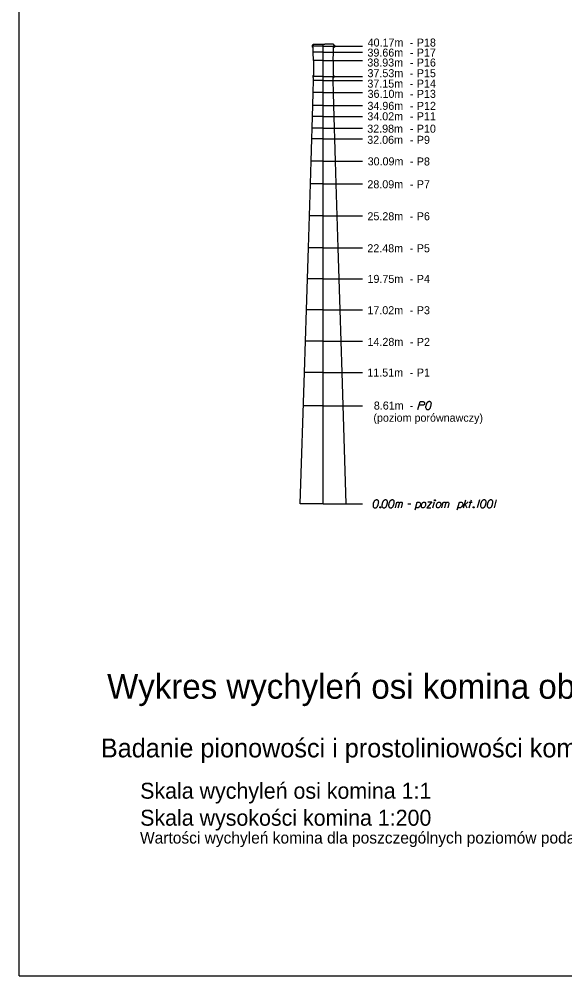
# Model space of a CAD drawing. Extents: x 138 to 264, y -75 to 121.
# Drawn here: x 196.41 to 206.91, y 2.29 to 20.71 of the extents above; entities that cross this region are included whole.
import ezdxf

# ---------------------------------------------------------------- set-up
doc = ezdxf.new("R2010")
doc.units = 0
doc.layers.add('Opisy', color=7, linetype='Continuous')
doc.layers.add('Ramka do drukowania', color=7, linetype='Continuous')

msp = doc.modelspace()

# ---------------------------------------------------------------- linework, layer by layer
at = {"layer": 'Opisy'}
for p, q in [((202.049, 20.204), (202.049, 20.185)), ((202.066, 20.204), (202.049, 20.204)), ((202.262, 20.185), (202.049, 20.185)), ((202.049, 20.185), (202.049, 20.166)), ((202.066, 20.166), (202.049, 20.166)), ((202.066, 20.222), (202.066, 20.204)), ((202.066, 20.222), (202.293, 20.222)), ((202.066, 20.072), (202.066, 20.166)), ((202.262, 11.376), (202.262, 20.222)), ((202.262, 20.185), (203.015, 20.185)), ((202.458, 20.222), (202.293, 20.222)), ((202.458, 20.222), (202.458, 20.204)), ((202.458, 20.204), (202.475, 20.204)), ((202.458, 20.166), (202.475, 20.166)), ((202.458, 20.072), (202.458, 20.166)), ((202.475, 20.204), (202.475, 20.185)), ((202.475, 20.185), (202.475, 20.166)), ((202.262, 20.072), (202.066, 20.072)), ((202.072, 19.912), (202.066, 20.072)), ((202.262, 19.912), (202.072, 19.912)), ((202.072, 19.912), (202.072, 19.624)), ((202.262, 20.072), (203.015, 20.072)), ((202.262, 19.912), (203.015, 19.912)), ((202.452, 19.912), (202.458, 20.072)), ((202.452, 19.912), (202.452, 19.624)), ((202.059, 19.624), (202.059, 19.605)), ((202.059, 19.624), (202.072, 19.624)), ((202.262, 19.605), (202.059, 19.605)), ((202.059, 19.605), (202.059, 19.586)), ((202.074, 19.586), (202.059, 19.586)), ((202.072, 19.522), (202.074, 19.586)), ((202.262, 19.605), (203.015, 19.605)), ((202.452, 19.522), (202.45, 19.586)), ((202.45, 19.586), (202.465, 19.586)), ((202.465, 19.624), (202.452, 19.624)), ((202.465, 19.624), (202.465, 19.605)), ((202.465, 19.605), (202.465, 19.586)), ((202.066, 19.291), (202.072, 19.522)), ((202.262, 19.522), (202.072, 19.522)), ((202.262, 19.522), (203.015, 19.522)), ((202.458, 19.291), (202.452, 19.522)), ((202.059, 19.041), (202.066, 19.291)), ((202.262, 19.291), (202.066, 19.291)), ((202.262, 19.291), (203.015, 19.291)), ((202.465, 19.041), (202.458, 19.291)), ((202.053, 18.835), (202.059, 19.041)), ((202.262, 19.041), (202.059, 19.041)), ((202.262, 19.041), (203.015, 19.041)), ((202.472, 18.835), (202.465, 19.041)), ((202.047, 18.607), (202.053, 18.835)), ((202.262, 18.835), (202.053, 18.835)), ((202.262, 18.835), (203.015, 18.835)), ((202.477, 18.607), (202.472, 18.835)), ((202.04, 18.405), (202.047, 18.607)), ((202.262, 18.607), (202.047, 18.607)), ((202.262, 18.607), (203.015, 18.607)), ((202.485, 18.405), (202.477, 18.607)), ((202.028, 17.973), (202.04, 18.405)), ((202.262, 18.405), (202.04, 18.405)), ((202.262, 18.405), (203.015, 18.405)), ((202.497, 17.973), (202.485, 18.405)), ((202.014, 17.535), (202.028, 17.973)), ((202.262, 17.973), (202.028, 17.973)), ((202.262, 17.973), (203.015, 17.973)), ((202.51, 17.535), (202.497, 17.973)), ((201.997, 16.918), (202.014, 17.535)), ((202.262, 17.535), (202.014, 17.535)), ((202.262, 17.535), (203.015, 17.535)), ((202.527, 16.918), (202.51, 17.535)), ((201.977, 16.305), (201.997, 16.918)), ((202.262, 16.918), (201.997, 16.918)), ((202.262, 16.918), (203.015, 16.918)), ((202.547, 16.305), (202.527, 16.918)), ((201.958, 15.706), (201.977, 16.305)), ((202.262, 16.305), (201.977, 16.305)), ((202.262, 16.305), (203.015, 16.305)), ((202.566, 15.706), (202.547, 16.305)), ((201.94, 15.108), (201.958, 15.706)), ((202.262, 15.706), (201.958, 15.706)), ((202.262, 15.706), (203.015, 15.706)), ((202.584, 15.108), (202.566, 15.706)), ((201.921, 14.506), (201.94, 15.108)), ((202.262, 15.108), (201.94, 15.108)), ((202.262, 15.108), (203.015, 15.108)), ((202.603, 14.506), (202.584, 15.108)), ((201.901, 13.9), (201.921, 14.506)), ((202.262, 14.506), (201.921, 14.506)), ((202.262, 14.506), (203.015, 14.506)), ((202.623, 13.9), (202.603, 14.506)), ((201.819, 11.376), (201.901, 13.9)), ((202.262, 13.9), (201.901, 13.9)), ((202.262, 13.9), (203.015, 13.9)), ((202.705, 11.376), (202.623, 13.9)), ((202.262, 13.263), (201.881, 13.263)), ((202.262, 13.263), (203.015, 13.263)), ((202.262, 11.376), (201.819, 11.376)), ((202.262, 11.376), (203.015, 11.376))]:
    msp.add_line(p, q, dxfattribs=at)
for points in [[(204.084, 13.189), (204.126, 13.343), (204.178, 13.343), (204.185, 13.342), (204.189, 13.34), (204.196, 13.337), (204.201, 13.333), (204.205, 13.328), (204.208, 13.322), (204.211, 13.314), (204.212, 13.306), (204.211, 13.3), (204.209, 13.295), (204.207, 13.291), (204.205, 13.287), (204.201, 13.282), (204.196, 13.278), (204.192, 13.276), (204.186, 13.274), (204.18, 13.272), (204.107, 13.272)], [(204.305, 13.343), (204.303, 13.343), (204.296, 13.342), (204.291, 13.34), (204.287, 13.339), (204.281, 13.337), (204.274, 13.333), (204.268, 13.329), (204.262, 13.325), (204.258, 13.32), (204.254, 13.314), (204.251, 13.308), (204.247, 13.3), (204.245, 13.295), (204.242, 13.288), (204.239, 13.276), (204.235, 13.258), (204.232, 13.243), (204.232, 13.23), (204.234, 13.22), (204.239, 13.209), (204.242, 13.203), (204.248, 13.196), (204.256, 13.191), (204.259, 13.19), (204.266, 13.189), (204.273, 13.189), (204.282, 13.19), (204.291, 13.192), (204.297, 13.196), (204.305, 13.202), (204.309, 13.206), (204.314, 13.21), (204.317, 13.215), (204.32, 13.219), (204.322, 13.225), (204.324, 13.227), (204.326, 13.234), (204.328, 13.241), (204.331, 13.248), (204.332, 13.253), (204.333, 13.257), (204.334, 13.261), (204.337, 13.272), (204.338, 13.278), (204.339, 13.285), (204.341, 13.293), (204.342, 13.304), (204.342, 13.308), (204.341, 13.312), (204.339, 13.317), (204.336, 13.325), (204.332, 13.329), (204.328, 13.333), (204.324, 13.337), (204.319, 13.339), (204.315, 13.34), (204.311, 13.342), (204.305, 13.343)], [(203.291, 11.45), (203.289, 11.45), (203.282, 11.449), (203.277, 11.448), (203.273, 11.447), (203.267, 11.444), (203.26, 11.441), (203.254, 11.437), (203.248, 11.432), (203.244, 11.427), (203.24, 11.421), (203.237, 11.415), (203.233, 11.408), (203.231, 11.403), (203.228, 11.396), (203.225, 11.384), (203.221, 11.365), (203.219, 11.351), (203.219, 11.337), (203.22, 11.328), (203.225, 11.317), (203.228, 11.311), (203.234, 11.303), (203.242, 11.299), (203.245, 11.297), (203.253, 11.296), (203.259, 11.296), (203.268, 11.297), (203.277, 11.3), (203.283, 11.303), (203.291, 11.31), (203.295, 11.313), (203.3, 11.318), (203.304, 11.323), (203.306, 11.327), (203.308, 11.333), (203.31, 11.335), (203.312, 11.341), (203.315, 11.348), (203.317, 11.356), (203.318, 11.361), (203.319, 11.364), (203.321, 11.369), (203.323, 11.38), (203.324, 11.386), (203.325, 11.392), (203.327, 11.401), (203.328, 11.412), (203.328, 11.415), (203.327, 11.42), (203.325, 11.425), (203.322, 11.432), (203.318, 11.437), (203.315, 11.441), (203.31, 11.444), (203.305, 11.447), (203.301, 11.448), (203.298, 11.449), (203.291, 11.45)], [(203.463, 11.45), (203.46, 11.45), (203.453, 11.449), (203.448, 11.448), (203.444, 11.447), (203.438, 11.444), (203.431, 11.441), (203.425, 11.437), (203.419, 11.432), (203.415, 11.427), (203.412, 11.421), (203.408, 11.415), (203.404, 11.408), (203.402, 11.403), (203.399, 11.396), (203.396, 11.384), (203.392, 11.365), (203.39, 11.351), (203.39, 11.337), (203.391, 11.328), (203.396, 11.317), (203.399, 11.311), (203.406, 11.303), (203.413, 11.299), (203.416, 11.297), (203.424, 11.296), (203.43, 11.296), (203.44, 11.297), (203.448, 11.3), (203.454, 11.303), (203.463, 11.31), (203.466, 11.313), (203.471, 11.318), (203.475, 11.323), (203.477, 11.327), (203.48, 11.333), (203.481, 11.335), (203.483, 11.341), (203.486, 11.348), (203.488, 11.356), (203.489, 11.361), (203.491, 11.364), (203.492, 11.369), (203.494, 11.38), (203.495, 11.386), (203.497, 11.392), (203.498, 11.401), (203.499, 11.412), (203.499, 11.415), (203.498, 11.42), (203.497, 11.425), (203.493, 11.432), (203.489, 11.437), (203.486, 11.441), (203.481, 11.444), (203.476, 11.447), (203.472, 11.448), (203.469, 11.449), (203.463, 11.45)], [(203.592, 11.45), (203.59, 11.45), (203.583, 11.449), (203.578, 11.448), (203.574, 11.447), (203.568, 11.444), (203.561, 11.441), (203.555, 11.437), (203.549, 11.432), (203.545, 11.427), (203.541, 11.421), (203.538, 11.415), (203.534, 11.408), (203.532, 11.403), (203.529, 11.396), (203.526, 11.384), (203.522, 11.365), (203.52, 11.351), (203.52, 11.337), (203.521, 11.328), (203.526, 11.317), (203.529, 11.311), (203.535, 11.303), (203.543, 11.299), (203.546, 11.297), (203.554, 11.296), (203.56, 11.296), (203.569, 11.297), (203.578, 11.3), (203.584, 11.303), (203.592, 11.31), (203.596, 11.313), (203.601, 11.318), (203.605, 11.323), (203.607, 11.327), (203.609, 11.333), (203.611, 11.335), (203.613, 11.341), (203.616, 11.348), (203.618, 11.356), (203.619, 11.361), (203.62, 11.364), (203.622, 11.369), (203.624, 11.38), (203.625, 11.386), (203.626, 11.392), (203.628, 11.401), (203.629, 11.412), (203.629, 11.415), (203.628, 11.42), (203.626, 11.425), (203.623, 11.432), (203.619, 11.437), (203.616, 11.441), (203.611, 11.444), (203.606, 11.447), (203.602, 11.448), (203.599, 11.449), (203.592, 11.45)], [(204.407, 11.45), (204.413, 11.45), (204.417, 11.448), (204.42, 11.443), (204.42, 11.437), (204.417, 11.432), (204.413, 11.43), (204.407, 11.43), (204.403, 11.432), (204.4, 11.437), (204.4, 11.443), (204.403, 11.448), (204.407, 11.45)], [(204.963, 11.296), (205.004, 11.45)], [(205.071, 11.296), (205.111, 11.45)], [(205.266, 11.45), (205.225, 11.296)], [(205.36, 11.45), (205.357, 11.45), (205.35, 11.449), (205.345, 11.448), (205.342, 11.447), (205.336, 11.444), (205.328, 11.441), (205.322, 11.437), (205.316, 11.432), (205.313, 11.427), (205.309, 11.421), (205.305, 11.415), (205.302, 11.408), (205.299, 11.403), (205.297, 11.396), (205.293, 11.384), (205.29, 11.365), (205.287, 11.351), (205.287, 11.337), (205.288, 11.328), (205.293, 11.317), (205.297, 11.311), (205.303, 11.303), (205.31, 11.299), (205.314, 11.297), (205.321, 11.296), (205.327, 11.296), (205.337, 11.297), (205.345, 11.3), (205.351, 11.303), (205.36, 11.31), (205.364, 11.313), (205.368, 11.318), (205.372, 11.323), (205.374, 11.327), (205.377, 11.333), (205.378, 11.335), (205.381, 11.341), (205.383, 11.348), (205.385, 11.356), (205.387, 11.361), (205.388, 11.364), (205.389, 11.369), (205.391, 11.38), (205.393, 11.386), (205.394, 11.392), (205.395, 11.401), (205.396, 11.412), (205.396, 11.415), (205.395, 11.42), (205.394, 11.425), (205.39, 11.432), (205.387, 11.437), (205.383, 11.441), (205.378, 11.444), (205.373, 11.447), (205.37, 11.448), (205.366, 11.449), (205.36, 11.45)], [(205.49, 11.45), (205.487, 11.45), (205.48, 11.449), (205.475, 11.448), (205.472, 11.447), (205.465, 11.444), (205.458, 11.441), (205.452, 11.437), (205.446, 11.432), (205.442, 11.427), (205.439, 11.421), (205.435, 11.415), (205.432, 11.408), (205.429, 11.403), (205.427, 11.396), (205.423, 11.384), (205.419, 11.365), (205.417, 11.351), (205.417, 11.337), (205.418, 11.328), (205.423, 11.317), (205.427, 11.311), (205.433, 11.303), (205.44, 11.299), (205.444, 11.297), (205.451, 11.296), (205.457, 11.296), (205.467, 11.297), (205.475, 11.3), (205.481, 11.303), (205.49, 11.31), (205.493, 11.313), (205.498, 11.318), (205.502, 11.323), (205.504, 11.327), (205.507, 11.333), (205.508, 11.335), (205.51, 11.341), (205.513, 11.348), (205.515, 11.356), (205.516, 11.361), (205.518, 11.364), (205.519, 11.369), (205.521, 11.38), (205.523, 11.386), (205.524, 11.392), (205.525, 11.401), (205.526, 11.412), (205.526, 11.415), (205.525, 11.42), (205.524, 11.425), (205.52, 11.432), (205.516, 11.437), (205.513, 11.441), (205.508, 11.444), (205.503, 11.447), (205.499, 11.448), (205.496, 11.449), (205.49, 11.45)], [(205.588, 11.45), (205.547, 11.296)], [(203.356, 11.317), (203.362, 11.317), (203.365, 11.314), (203.369, 11.31), (203.369, 11.303), (203.365, 11.299), (203.362, 11.296), (203.356, 11.296), (203.352, 11.299), (203.348, 11.303), (203.348, 11.31), (203.352, 11.314), (203.356, 11.317)], [(203.649, 11.296), (203.677, 11.407)], [(203.67, 11.378), (203.676, 11.391), (203.682, 11.398), (203.69, 11.403), (203.697, 11.407), (203.702, 11.409), (203.709, 11.409), (203.711, 11.408), (203.716, 11.403), (203.721, 11.397), (203.725, 11.386), (203.726, 11.38), (203.732, 11.391), (203.739, 11.398), (203.747, 11.403), (203.754, 11.407), (203.76, 11.409), (203.766, 11.409), (203.771, 11.408), (203.775, 11.403), (203.778, 11.397), (203.782, 11.386), (203.783, 11.38), (203.762, 11.296)], [(203.705, 11.296), (203.726, 11.38)], [(203.892, 11.374), (203.945, 11.374)], [(204.027, 11.256), (204.068, 11.408)], [(204.065, 11.395), (204.077, 11.404), (204.095, 11.408), (204.11, 11.405), (204.119, 11.398), (204.127, 11.388), (204.132, 11.375), (204.133, 11.363), (204.13, 11.352), (204.127, 11.339), (204.117, 11.324), (204.105, 11.311), (204.087, 11.299), (204.071, 11.296), (204.056, 11.297), (204.04, 11.306)], [(204.201, 11.408), (204.209, 11.408), (204.219, 11.403), (204.229, 11.39), (204.23, 11.384), (204.231, 11.378), (204.231, 11.373), (204.231, 11.354), (204.227, 11.342), (204.221, 11.328), (204.214, 11.316), (204.202, 11.305), (204.191, 11.296), (204.173, 11.296), (204.166, 11.299), (204.158, 11.305), (204.155, 11.311), (204.15, 11.325), (204.15, 11.347), (204.152, 11.354), (204.157, 11.37), (204.162, 11.379), (204.164, 11.384), (204.176, 11.397), (204.189, 11.404), (204.201, 11.408)], [(204.274, 11.41), (204.352, 11.41), (204.252, 11.296), (204.329, 11.296)], [(204.373, 11.296), (204.405, 11.414)], [(204.492, 11.408), (204.501, 11.408), (204.51, 11.403), (204.52, 11.39), (204.521, 11.384), (204.522, 11.378), (204.522, 11.373), (204.522, 11.354), (204.519, 11.342), (204.513, 11.328), (204.505, 11.316), (204.493, 11.305), (204.482, 11.296), (204.464, 11.296), (204.457, 11.299), (204.45, 11.305), (204.446, 11.311), (204.441, 11.325), (204.441, 11.347), (204.443, 11.354), (204.448, 11.37), (204.453, 11.379), (204.456, 11.384), (204.468, 11.397), (204.48, 11.404), (204.492, 11.408)], [(204.543, 11.296), (204.571, 11.407)], [(204.564, 11.378), (204.57, 11.391), (204.576, 11.398), (204.583, 11.403), (204.59, 11.407), (204.595, 11.409), (204.602, 11.409), (204.605, 11.408), (204.61, 11.403), (204.615, 11.397), (204.618, 11.386), (204.619, 11.38), (204.626, 11.391), (204.633, 11.398), (204.64, 11.403), (204.647, 11.407), (204.653, 11.409), (204.66, 11.409), (204.664, 11.408), (204.668, 11.403), (204.672, 11.397), (204.675, 11.386), (204.677, 11.38), (204.656, 11.296)], [(204.599, 11.296), (204.619, 11.38)], [(204.84, 11.256), (204.882, 11.408)], [(204.878, 11.395), (204.89, 11.404), (204.908, 11.408), (204.923, 11.405), (204.933, 11.398), (204.94, 11.388), (204.945, 11.375), (204.946, 11.363), (204.944, 11.352), (204.94, 11.339), (204.93, 11.324), (204.918, 11.311), (204.9, 11.299), (204.884, 11.296), (204.87, 11.297), (204.854, 11.306)], [(204.978, 11.351), (205.05, 11.412)], [(204.992, 11.363), (205.024, 11.296)], [(205.071, 11.408), (205.129, 11.408)], [(205.15, 11.317), (205.156, 11.317), (205.16, 11.314), (205.163, 11.31), (205.163, 11.303), (205.16, 11.299), (205.156, 11.296), (205.15, 11.296), (205.146, 11.299), (205.143, 11.303), (205.143, 11.31), (205.146, 11.314), (205.15, 11.317)]]:
    msp.add_lwpolyline(points, dxfattribs=at)
at = {"layer": 'Ramka do drukowania'}
for q in [(196.41, 31.985), (217.41, 2.285)]:
    msp.add_line((196.41, 2.285), q, dxfattribs=at)

# ---------------------------------------------------------------- texts
at = {"layer": 'Opisy'}
for s, height, p in [('40.17m', 0.1542, (203.115, 20.179)), ('P18', 0.1542, (204.062, 20.179)), ('39.66m', 0.1542, (203.112, 19.985)), ('-', 0.154, (203.925, 20.179)), ('P17', 0.1542, (204.062, 19.985)), ('38.93m', 0.1542, (203.11, 19.794)), ('-', 0.154, (203.927, 19.985)), ('P16', 0.1542, (204.062, 19.794)), ('37.53m', 0.1542, (203.113, 19.589)), ('-', 0.154, (203.929, 19.794)), ('P15', 0.1542, (204.062, 19.589)), ('37.15m', 0.1542, (203.111, 19.388)), ('-', 0.154, (203.925, 19.589)), ('P14', 0.1542, (204.062, 19.388)), ('36.10m', 0.1542, (203.115, 19.191)), ('-', 0.154, (203.925, 19.388)), ('P13', 0.1542, (204.062, 19.191)), ('-', 0.154, (203.927, 19.191)), ('34.96m', 0.1542, (203.112, 18.96)), ('-', 0.154, (203.927, 18.96)), ('P12', 0.1542, (204.063, 18.96)), ('34.02m', 0.1542, (203.11, 18.759)), ('-', 0.154, (203.927, 18.759)), ('P11', 0.1542, (204.062, 18.759)), ('32.98m', 0.1542, (203.108, 18.52)), ('P10', 0.1542, (204.062, 18.52)), ('32.06m', 0.1542, (203.108, 18.306)), ('-', 0.154, (203.927, 18.52)), ('P9', 0.1542, (204.062, 18.306)), ('-', 0.154, (203.927, 18.306)), ('30.09m', 0.1542, (203.116, 17.891)), ('-', 0.154, (203.927, 17.891)), ('P8', 0.1542, (204.062, 17.889)), ('28.09m', 0.1542, (203.111, 17.45)), ('-', 0.154, (203.927, 17.45)), ('P7', 0.1542, (204.062, 17.45)), ('25.28m', 0.1542, (203.112, 16.834)), ('P6', 0.1542, (204.062, 16.834)), ('-', 0.154, (203.925, 16.834)), ('22.48m', 0.1542, (203.11, 16.218)), ('-', 0.154, (203.925, 16.218)), ('P5', 0.1542, (204.062, 16.218)), ('19.75m', 0.1542, (203.113, 15.628)), ('-', 0.154, (203.925, 15.628)), ('P4', 0.1542, (204.062, 15.628)), ('17.02m', 0.1542, (203.111, 15.025)), ('P3', 0.1542, (204.062, 15.025)), ('-', 0.154, (203.925, 15.025)), ('14.28m', 0.1542, (203.113, 14.415)), ('P2', 0.1542, (204.062, 14.415)), ('-', 0.154, (203.926, 14.415)), ('11.51m', 0.1542, (203.11, 13.825)), ('-', 0.154, (203.925, 13.825)), ('P1', 0.1542, (204.063, 13.825)), ('8.61m', 0.1542, (203.235, 13.189)), ('(poziom porównawczy)', 0.15416, (203.227, 12.955)), ('-', 0.154, (203.925, 13.189)), ('Wykres wychyleń osi komina obserwowanych ze stanowiska 1001', 0.47516, (198.103, 7.621)), ('Badanie pionowości i prostoliniowości komina zakładu ceramicznego "Ceramika Stróże"', 0.36281, (197.983, 6.492)), ('Skala wychyleń osi komina 1:1', 0.30766, (198.739, 5.696)), ('Skala wysokości komina 1:200', 0.30766, (198.739, 5.176)), ('Wartości wychyleń komina dla poszczególnych poziomów podano w milimetrach', 0.22315, (198.736, 4.833))]:
    msp.add_text(s, height=height, dxfattribs=at).set_placement(p)

doc.saveas('drawing.dxf')
